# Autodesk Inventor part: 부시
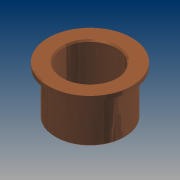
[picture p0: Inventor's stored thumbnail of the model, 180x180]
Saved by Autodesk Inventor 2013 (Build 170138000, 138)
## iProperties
Created: 2013-06
Part Number: 부시
Document SubType Name: Modeling
Designer: SeoGD™[esajin.kr]
Density: 7.86 g/cm^3
Material: 강철, 연강
Mass: 246.97 g
Surface Area: 129.264 cm^2
Volume: 31.4212 cm^3
Author: SeoGD™[esajin.kr]
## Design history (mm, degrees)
sketch "스케치1"
  geometry: C1 r 31 at (0, 0) reference; C2 r 25 at (0, 0) reference; C3 r 30 at (0, 0) reference; 1 further point
  node "참조1"
  node "참조2"
  node "참조4"
extrude "돌출1" new body sketch "스케치1" distance "d0" = 3; taper "d1" = 0 deg
extrude "돌출2" join sketch "스케치1" distance "d2" = 35; taper "d3" = 0 deg
chamfer "모따기1" distance "d6" = 1; stored, may be unused: second distance "d7" = 2, angle "d8" = 45 deg
sketch "스케치3"
  geometry: C1 r 19 at (0, 0); 1 further point
  constraints: 1 centre point, 1 coincident
  dimensions: "d13" = 38 diameter of C1
extrude "돌출4" cut sketch "스케치3" stored distance "d14" = 10; taper "d15" = 0 deg
chamfer "모따기3" distance "d16" = 1; stored, may be unused: second distance "d17" = 2, angle "d18" = 45 deg
node "솔리드1"
